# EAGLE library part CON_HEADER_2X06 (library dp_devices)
2x5 Pin header
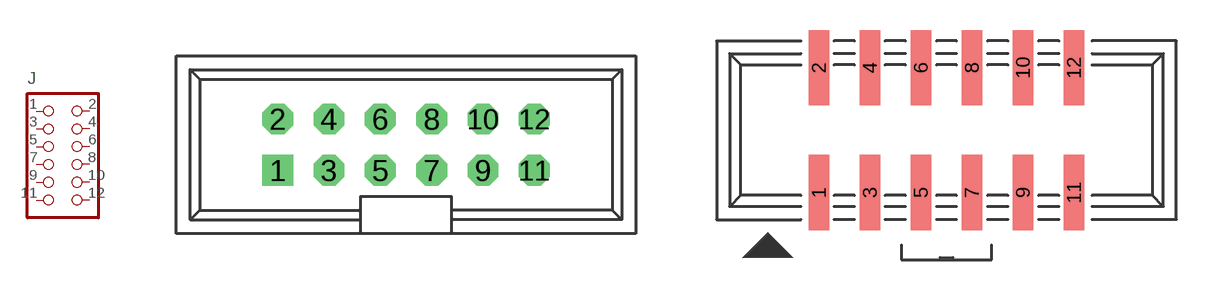
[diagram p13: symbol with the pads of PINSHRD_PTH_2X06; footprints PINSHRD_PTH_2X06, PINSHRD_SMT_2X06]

Designator prefix J

## CON_HEADER_2X06-PTH+SHROUDED  [PINSHRD_PTH_2X06]
1  1  pas
2  2  pas
3  3  pas
4  4  pas
5  5  pas
6  6  pas
7  7  pas
8  8  pas
9  9  pas
10  10  pas
11  11  pas
12  12  pas

## CON_HEADER_2X06-SMD+SHROUDED  [PINSHRD_SMT_2X06]
Pads as for PINSHRD_PTH_2X06

## Footprint PINSHRD_PTH_2X06 (pad centres in mm)
PIN HEADER - 2.54
drill 1.016 square: 1 -6.35,-1.27
drill 1.016 octagon: 2 -6.35,1.27; 3 -3.81,-1.27; 4 -3.81,1.27; 5 -1.27,-1.27; 6 -1.27,1.27; 7 1.27,-1.27; 8 1.27,1.27; 9 3.81,-1.27; 10 3.81,1.27; 11 6.35,-1.27; 12 6.35,1.27

## Footprint PINSHRD_SMT_2X06 (pad centres in mm)
pitch = 0.100 [2.54], 2x5 source: http://www.mlelectronic.com/shrouded-headers/shrouded-headers-100.asp
smd 1.02 x 3.75: 1 -6.35,-3.107; 2 -6.35,3.107; 3 -3.81,-3.107; 4 -3.81,3.107; 5 -1.27,-3.107; 6 -1.27,3.107; 7 1.27,-3.107; 8 1.27,3.107; 9 3.81,-3.107; 10 3.81,3.107; 11 6.35,-3.107; 12 6.35,3.107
